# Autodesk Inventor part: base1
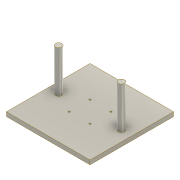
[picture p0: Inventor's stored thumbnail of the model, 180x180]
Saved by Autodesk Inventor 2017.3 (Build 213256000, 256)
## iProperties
Part Number: base1
Material: チタン
Document SubType Name: Modeling
Designer: kyushu-hep
Density: 4.51 g/cm^3
Appearance: チタン
Author: kyushu-hep
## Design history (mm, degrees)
sketch "スケッチ3"
  geometry: L1 (-100, 100)-(100, 100); L2 (100, 100)-(100, -100); L3 (100, -100)-(-100, -100); L4 (-100, -100)-(-100, 100); 1 further point
  constraints: 8 end point, 2 parallel, 1 horizontal, 1 perpendicular
  dimensions: "d19" = 100 distance from line of L1 point (0, 0); "d20" = 200 distance of L3.end L1.start; "d21" = 200 distance of L1.start L1.end; "d22" = 100 distance from line of L4 point (0, 0)
extrude "押し出し3" new body sketch "スケッチ3" distance "d23" = 10; taper "d24" = 0 deg
sketch "スケッチ4"
  geometry: C1 r 7.5 at (-75, 0); C2 r 7.5 at (75, 0); 1 further point
  constraints: 2 centre point
  dimensions: "d55" = 15 diameter of C1; "d57" = 15 diameter of C2; "d58" = 0 vertical distance of point (0, 0) C1.centre; "d59" = 75 distance of point (0, 0) C1.centre; "d62" = 0 vertical distance of point (0, 0) C2.centre; "d65" = 75 distance of C2.centre point (0, 0)
sketch "スケッチ6"
  geometry: L1 (52, -52)-(-52, -52); L2 (-52, -52)-(-52, 52); L3 (-52, 52)-(52, 52); L4 (52, 52)-(52, -52); L5 (52, -52)-(-52, 52); L6 (-52, -52)-(52, 52); C1 r 2 at (-25, 25); C2 r 2 at (25, 25); C3 r 2 at (-25, -25); C4 r 2 at (25, -25); 1 further point
  constraints: 12 end point, 4 centre point, 2 horizontal, 2 midpoint, 2 parallel, 1 perpendicular, 1 vertical, 6 other
  dimensions: "d38" = 4 diameter of C1; "d40" = 25 horizontal distance of point (0, 0) C1.centre; "d43" = 50 distance of C1.centre C2.centre; "d46" = 50 distance of C1.centre C3.centre; "d51" = 25 horizontal distance of point (0, 0) C2.centre
extrude "押し出し6" cut sketch "スケッチ6" distance "d49" = 10; taper "d50" = 0 deg
extrude "押し出し8" join sketch "スケッチ4" distance "d63" = 100; taper "d64" = 0 deg
node "ソリッド2"
